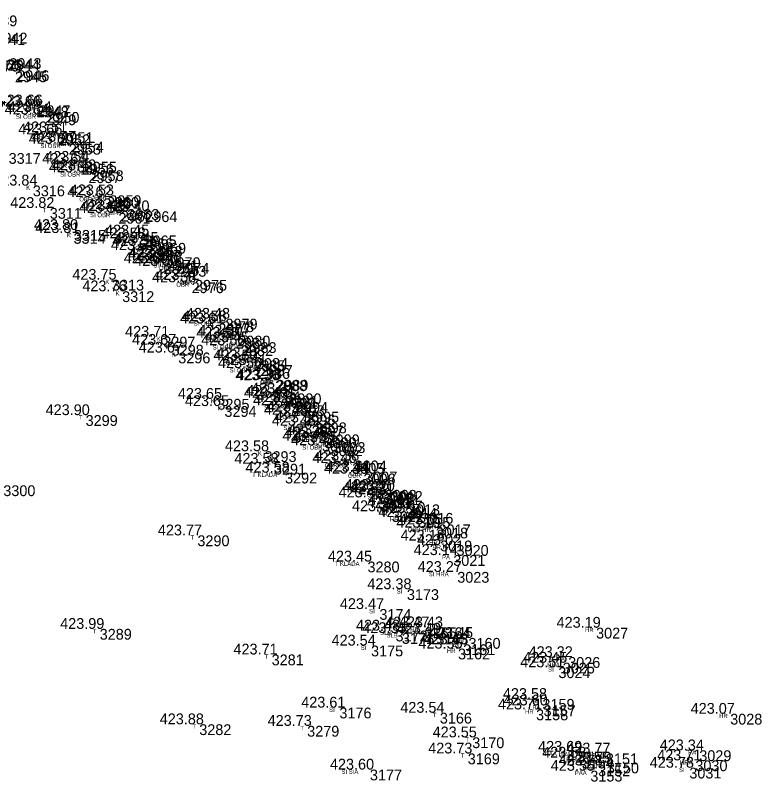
# Model space of a CAD drawing. Extents: x -639390 to -639075, y -1138747 to -1138358.
# Drawn here: x -639236.5 to -639184.6, y -1138516.9 to -1138463.7 of the extents above; entities that cross this region are included whole.
import ezdxf

# ---------------------------------------------------------------- set-up
doc = ezdxf.new("R2010")
doc.units = 0
for name, color, linetype in [('Vrstva 11', 7, 'Continuous'), ('Vrstva 12', 7, 'Continuous'), ('Vrstva 13', 7, 'Continuous'), ('Vrstva 57', 7, 'Continuous')]:
    doc.layers.add(name, color=color, linetype=linetype)

msp = doc.modelspace()

# ---------------------------------------------------------------- linework, layer by layer
at = {"layer": 'Vrstva 11'}
for p, q in [((-639235.32, -1138470), (-639235.32, -1138470)), ((-639235.19, -1138469.92), (-639235.19, -1138469.92)), ((-639234.79, -1138470.55), (-639234.79, -1138470.55)), ((-639234.57, -1138470.38), (-639234.57, -1138470.38)), ((-639233.83, -1138471.94), (-639233.83, -1138471.94)), ((-639233.6, -1138471.79), (-639233.6, -1138471.79)), ((-639233.08, -1138472.59), (-639233.08, -1138472.59)), ((-639232.88, -1138472.45), (-639232.88, -1138472.45)), ((-639232.18, -1138473.98), (-639232.18, -1138473.98)), ((-639231.97, -1138473.84), (-639231.97, -1138473.84)), ((-639231.71, -1138474.57), (-639231.71, -1138474.57)), ((-639231.5, -1138474.43), (-639231.5, -1138474.43)), ((-639235.58, -1138475.49), (-639235.58, -1138475.49)), ((-639230.43, -1138476.29), (-639230.43, -1138476.29)), ((-639230.26, -1138476.17), (-639230.26, -1138476.17)), ((-639234.4, -1138477.05), (-639234.4, -1138477.05)), ((-639229.63, -1138477.39), (-639229.63, -1138477.39)), ((-639229.46, -1138477.25), (-639229.46, -1138477.25)), ((-639229.02, -1138477.13), (-639229.02, -1138477.13)), ((-639227.76, -1138477.28), (-639227.76, -1138477.28)), ((-639232.75, -1138478.79), (-639232.75, -1138478.79)), ((-639232.72, -1138478.58), (-639232.72, -1138478.58)), ((-639227.81, -1138478.96), (-639227.81, -1138478.96)), ((-639228.05, -1138479.16), (-639228.05, -1138479.16)), ((-639227.16, -1138479.48), (-639227.16, -1138479.48)), ((-639227.5, -1138479.98), (-639227.5, -1138479.98)), ((-639227.4, -1138479.69), (-639227.4, -1138479.69)), ((-639226.3, -1138480.66), (-639226.3, -1138480.66)), ((-639226.15, -1138480.48), (-639226.15, -1138480.48)), ((-639226.48, -1138480.89), (-639226.48, -1138480.89)), ((-639225.75, -1138481.08), (-639225.75, -1138481.08)), ((-639225.54, -1138480.87), (-639225.54, -1138480.87)), ((-639230.08, -1138482.04), (-639230.08, -1138482.04)), ((-639224.54, -1138482.22), (-639224.54, -1138482.22)), ((-639224.31, -1138482.05), (-639224.31, -1138482.05)), ((-639229.37, -1138482.84), (-639229.37, -1138482.84)), ((-639222.43, -1138484.93), (-639222.43, -1138484.93)), ((-639222.19, -1138484.75), (-639222.19, -1138484.75)), ((-639222.69, -1138485.08), (-639222.69, -1138485.08)), ((-639226.51, -1138486), (-639226.51, -1138486)), ((-639221.3, -1138485.93), (-639221.3, -1138485.93)), ((-639221.47, -1138486.07), (-639221.47, -1138486.07)), ((-639220.87, -1138486.38), (-639220.87, -1138486.38)), ((-639225.93, -1138486.56), (-639225.93, -1138486.56)), ((-639221.11, -1138486.59), (-639221.11, -1138486.59)), ((-639225.47, -1138487.1), (-639225.47, -1138487.1)), ((-639220.07, -1138487.49), (-639220.07, -1138487.49)), ((-639220.25, -1138487.64), (-639220.25, -1138487.64)), ((-639219.74, -1138487.97), (-639219.74, -1138487.97)), ((-639219.93, -1138488.18), (-639219.93, -1138488.18)), ((-639218.73, -1138489.03), (-639218.73, -1138489.03)), ((-639218.66, -1138489), (-639218.66, -1138489)), ((-639218.16, -1138490.24), (-639218.16, -1138490.24)), ((-639217.99, -1138490.11), (-639217.99, -1138490.11)), ((-639217.75, -1138489.94), (-639217.75, -1138489.94)), ((-639222.75, -1138490.32), (-639222.75, -1138490.32)), ((-639217.53, -1138490.77), (-639217.53, -1138490.77)), ((-639217.29, -1138490.54), (-639217.29, -1138490.54)), ((-639222.26, -1138490.82), (-639222.26, -1138490.82)), ((-639216.52, -1138491.21), (-639216.52, -1138491.21)), ((-639231.91, -1138491.45), (-639231.91, -1138491.45)), ((-639216.77, -1138491.42), (-639216.77, -1138491.42)), ((-639216.2, -1138492.19), (-639216.2, -1138492.19)), ((-639215.99, -1138491.96), (-639215.99, -1138491.96)), ((-639215.09, -1138492.79), (-639215.09, -1138492.79)), ((-639215.48, -1138493.23), (-639215.48, -1138493.23)), ((-639215.31, -1138493), (-639215.31, -1138493)), ((-639214.69, -1138493.33), (-639214.69, -1138493.33)), ((-639219.48, -1138493.96), (-639219.48, -1138493.96)), ((-639214.88, -1138493.55), (-639214.88, -1138493.55)), ((-639218.82, -1138494.83), (-639218.82, -1138494.83)), ((-639213.38, -1138494.78), (-639213.38, -1138494.78)), ((-639213.21, -1138494.61), (-639213.21, -1138494.61)), ((-639218.05, -1138495.45), (-639218.05, -1138495.45)), ((-639212.6, -1138495.51), (-639212.6, -1138495.51)), ((-639212.48, -1138495.38), (-639212.48, -1138495.38)), ((-639211.13, -1138496.65), (-639211.13, -1138496.65)), ((-639211.58, -1138497.17), (-639211.58, -1138497.17)), ((-639211.3, -1138496.82), (-639211.3, -1138496.82)), ((-639210.88, -1138496.95), (-639210.88, -1138496.95)), ((-639210.71, -1138496.73), (-639210.71, -1138496.73)), ((-639209.51, -1138497.66), (-639209.51, -1138497.66)), ((-639210.63, -1138498.13), (-639210.63, -1138498.13)), ((-639209.71, -1138497.9), (-639209.71, -1138497.9)), ((-639208.58, -1138498.25), (-639208.58, -1138498.25)), ((-639208.79, -1138498.54), (-639208.79, -1138498.54)), ((-639207.56, -1138499.27), (-639207.56, -1138499.27)), ((-639207.38, -1138499.05), (-639207.38, -1138499.05)), ((-639224.14, -1138499.81), (-639224.14, -1138499.81)), ((-639207.27, -1138500.17), (-639207.27, -1138500.17)), ((-639206.13, -1138500.48), (-639206.13, -1138500.48)), ((-639206.36, -1138501.18), (-639206.36, -1138501.18)), ((-639212.32, -1138501.63), (-639212.32, -1138501.63)), ((-639206.08, -1138502.35), (-639206.08, -1138502.35)), ((-639209.58, -1138503.55), (-639209.58, -1138503.55)), ((-639211.49, -1138504.93), (-639211.49, -1138504.93)), ((-639208.34, -1138506.21), (-639208.34, -1138506.21)), ((-639207.39, -1138506.2), (-639207.39, -1138506.2)), ((-639196.43, -1138506.23), (-639196.43, -1138506.23)), ((-639230.93, -1138506.31), (-639230.93, -1138506.31)), ((-639210.37, -1138506.43), (-639210.37, -1138506.43)), ((-639209.93, -1138506.6), (-639209.93, -1138506.6)), ((-639207.53, -1138506.64), (-639207.53, -1138506.64)), ((-639205.3, -1138506.94), (-639205.3, -1138506.94)), ((-639212.07, -1138507.47), (-639212.07, -1138507.47)), ((-639206.03, -1138507.68), (-639206.03, -1138507.68)), ((-639205.67, -1138507.38), (-639205.67, -1138507.38)), ((-639218.98, -1138508.09), (-639218.98, -1138508.09)), ((-639198.37, -1138508.27), (-639198.37, -1138508.27)), ((-639198.75, -1138508.66), (-639198.75, -1138508.66)), ((-639199.05, -1138508.98), (-639199.05, -1138508.98)), ((-639200.16, -1138511.18), (-639200.16, -1138511.18)), ((-639214.27, -1138511.78), (-639214.27, -1138511.78)), ((-639200.6, -1138511.91), (-639200.6, -1138511.91)), ((-639200.08, -1138511.63), (-639200.08, -1138511.63)), ((-639207.29, -1138512.14), (-639207.29, -1138512.14)), ((-639187.11, -1138512.21), (-639187.11, -1138512.21)), ((-639224.01, -1138512.94), (-639224.01, -1138512.94)), ((-639216.51, -1138513.05), (-639216.51, -1138513.05)), ((-639205.04, -1138513.85), (-639205.04, -1138513.85)), ((-639189.26, -1138514.75), (-639189.26, -1138514.75)), ((-639205.35, -1138514.97), (-639205.35, -1138514.97)), ((-639197.71, -1138514.85), (-639197.71, -1138514.85)), ((-639197.43, -1138515.26), (-639197.43, -1138515.26)), ((-639195.75, -1138514.97), (-639195.75, -1138514.97)), ((-639196.29, -1138515.8), (-639196.29, -1138515.8)), ((-639195.68, -1138515.6), (-639195.68, -1138515.6)), ((-639189.53, -1138515.45), (-639189.53, -1138515.45)), ((-639212.15, -1138516.09), (-639212.15, -1138516.09)), ((-639196.83, -1138516.17), (-639196.83, -1138516.17)), ((-639189.95, -1138515.96), (-639189.95, -1138515.96))]:
    msp.add_line(p, q, dxfattribs=at)

# ---------------------------------------------------------------- texts
at = {"layer": 'Vrstva 12'}
for s, p in [('423.70 ', (-639239.319, -1138467.56)), ('423.66 ', (-639239.146, -1138467.48)), ('423.66 ', (-639237.806, -1138470)), ('423.66 ', (-639237.676, -1138469.92)), ('423.64 ', (-639237.259, -1138470.55)), ('423.54 ', (-639237.039, -1138470.38)), ('423.51 ', (-639235.975, -1138471.79)), ('423.66 ', (-639236.316, -1138471.94)), ('423.60 ', (-639235.579, -1138472.59)), ('423.47 ', (-639235.349, -1138472.45)), ('423.54 ', (-639234.439, -1138473.84)), ('423.64 ', (-639234.649, -1138473.98)), ('423.48 ', (-639233.969, -1138474.43)), ('423.63 ', (-639234.179, -1138474.57)), ('423.84 ', (-639238.049, -1138475.49)), ('423.62 ', (-639232.899, -1138476.29)), ('423.53 ', (-639232.729, -1138476.17)), ('423.82 ', (-639236.869, -1138477.05)), ('423.40 ', (-639231.519, -1138477.13)), ('423.58 ', (-639232.099, -1138477.39)), ('423.45 ', (-639231.93, -1138477.25)), ('423.40 ', (-639230.259, -1138477.28)), ('423.80 ', (-639235.219, -1138478.58)), ('423.81 ', (-639235.125, -1138478.79)), ('423.58 ', (-639230.519, -1138479.16)), ('423.45 ', (-639230.28, -1138478.96)), ('423.51 ', (-639229.775, -1138479.69)), ('423.45 ', (-639229.63, -1138479.48)), ('423.61 ', (-639229.875, -1138479.98)), ('423.60 ', (-639228.979, -1138480.89)), ('423.51 ', (-639228.675, -1138480.66)), ('423.45 ', (-639228.62, -1138480.48)), ('423.40 ', (-639228.039, -1138480.87)), ('423.50 ', (-639228.249, -1138481.08)), ('423.75 ', (-639232.55, -1138482.04)), ('423.58 ', (-639227.009, -1138482.22)), ('423.42 ', (-639226.779, -1138482.05)), ('423.76 ', (-639231.856, -1138482.84)), ('423.61 ', (-639225.065, -1138485.08)), ('423.58 ', (-639224.899, -1138484.93)), ('423.48 ', (-639224.659, -1138484.75)), ('423.71 ', (-639228.885, -1138486)), ('423.57 ', (-639223.939, -1138486.07)), ('423.50 ', (-639223.799, -1138485.93)), ('423.67 ', (-639228.399, -1138486.56)), ('423.56 ', (-639223.596, -1138486.59)), ('423.45 ', (-639223.34, -1138486.38)), ('423.67 ', (-639227.939, -1138487.1)), ('423.50 ', (-639222.749, -1138487.64)), ('423.42 ', (-639222.539, -1138487.49)), ('423.50 ', (-639222.429, -1138488.18)), ('423.41 ', (-639222.115, -1138487.97)), ('423.36 ', (-639221.216, -1138489.03)), ('423.33 ', (-639221.129, -1138489)), ('423.31 ', (-639220.125, -1138489.94)), ('423.65 ', (-639225.22, -1138490.32)), ('423.49 ', (-639220.629, -1138490.24)), ('423.45 ', (-639220.46, -1138490.11)), ('423.65 ', (-639224.73, -1138490.82)), ('423.48 ', (-639219.999, -1138490.77)), ('423.34 ', (-639219.759, -1138490.54)), ('423.90 ', (-639234.409, -1138491.45)), ('423.43 ', (-639219.239, -1138491.42)), ('423.30 ', (-639219.019, -1138491.21)), ('423.36 ', (-639218.476, -1138491.96)), ('423.46 ', (-639218.686, -1138492.19)), ('423.46 ', (-639217.796, -1138493)), ('423.35 ', (-639217.56, -1138492.79)), ('423.48 ', (-639217.949, -1138493.23)), ('423.47 ', (-639217.349, -1138493.55)), ('423.35 ', (-639217.16, -1138493.33)), ('423.58 ', (-639221.949, -1138493.96)), ('423.38 ', (-639215.679, -1138494.61)), ('423.58 ', (-639221.289, -1138494.83)), ('423.46 ', (-639215.866, -1138494.78)), ('423.58 ', (-639220.519, -1138495.45)), ('423.44 ', (-639215.069, -1138495.51)), ('423.44 ', (-639214.949, -1138495.38)), ('423.32 ', (-639213.769, -1138496.82)), ('423.26 ', (-639213.616, -1138496.65)), ('423.20 ', (-639213.209, -1138496.73)), ('423.43 ', (-639214.049, -1138497.17)), ('423.31 ', (-639213.255, -1138496.95)), ('423.31 ', (-639212.085, -1138497.9)), ('423.15 ', (-639211.98, -1138497.66)), ('423.36 ', (-639213.116, -1138498.13)), ('423.10 ', (-639211.079, -1138498.25)), ('423.26 ', (-639211.276, -1138498.54)), ('423.19 ', (-639210.029, -1138499.27)), ('423.05 ', (-639209.85, -1138499.05)), ('423.77 ', (-639226.609, -1138499.81)), ('423.18 ', (-639209.739, -1138500.17)), ('423.02 ', (-639208.599, -1138500.48)), ('423.45 ', (-639214.79, -1138501.63)), ('423.14 ', (-639208.829, -1138501.18)), ('423.27 ', (-639208.549, -1138502.35)), ('423.38 ', (-639212.049, -1138503.55)), ('423.47 ', (-639213.959, -1138504.93)), ('423.99 ', (-639233.399, -1138506.31)), ('423.48 ', (-639212.839, -1138506.43)), ('423.47 ', (-639210.809, -1138506.21)), ('423.43 ', (-639209.859, -1138506.2)), ('423.19 ', (-639198.899, -1138506.23)), ('423.35 ', (-639212.4, -1138506.6)), ('423.49 ', (-639209.999, -1138506.64)), ('423.45 ', (-639207.77, -1138506.94)), ('423.54 ', (-639214.539, -1138507.47)), ('423.45 ', (-639208.14, -1138507.38)), ('423.55 ', (-639208.5, -1138507.68)), ('423.71 ', (-639221.355, -1138508.09)), ('423.32 ', (-639200.839, -1138508.27)), ('423.51 ', (-639201.425, -1138508.98)), ('423.45 ', (-639201.22, -1138508.66)), ('423.58 ', (-639202.629, -1138511.18)), ('423.61 ', (-639216.645, -1138511.78)), ('423.60 ', (-639202.579, -1138511.63)), ('423.54 ', (-639209.759, -1138512.14)), ('423.71 ', (-639202.975, -1138511.91)), ('423.07 ', (-639189.579, -1138512.21)), ('423.88 ', (-639226.479, -1138512.94)), ('423.73 ', (-639218.979, -1138513.05)), ('423.55 ', (-639207.51, -1138513.85)), ('423.73 ', (-639207.819, -1138514.97)), ('423.69 ', (-639200.179, -1138514.85)), ('423.77 ', (-639198.219, -1138514.97)), ('423.34 ', (-639191.729, -1138514.75)), ('423.58 ', (-639199.899, -1138515.26)), ('423.71 ', (-639191.905, -1138515.45)), ('423.78 ', (-639198.759, -1138515.8)), ('423.79 ', (-639198.149, -1138515.6)), ('423.78 ', (-639192.419, -1138515.96)), ('423.60 ', (-639214.649, -1138516.09)), ('423.55 ', (-639199.3, -1138516.17))]:
    msp.add_text(s, height=0.75, dxfattribs=at).set_placement(p)
at = {"layer": 'Vrstva 13'}
for s, p in [(' 2939', (-639238.89, -1138464.42)), (' 2941', (-639238.34, -1138465.73)), (' 2942', (-639238.18, -1138465.62)), (' 2944', (-639237.33, -1138467.51)), (' 2943', (-639237.21, -1138467.39)), (' 2945', (-639236.82, -1138468.31)), (' 2946', (-639236.66, -1138468.23)), (' 2948', (-639235.32, -1138470.75)), (' 2947', (-639235.19, -1138470.67)), (' 2949', (-639234.79, -1138471.3)), (' 2950', (-639234.57, -1138471.13)), (' 2952', (-639233.83, -1138472.69)), (' 2951', (-639233.6, -1138472.54)), (' 2953', (-639233.08, -1138473.34)), (' 2954', (-639232.88, -1138473.2)), (' 3317', (-639237.26, -1138473.98)), (' 2956', (-639232.18, -1138474.73)), (' 2955', (-639231.97, -1138474.59)), (' 2957', (-639231.71, -1138475.32)), (' 2958', (-639231.5, -1138475.18)), (' 3316', (-639235.58, -1138476.24)), (' 2960', (-639230.43, -1138477.04)), (' 2959', (-639230.26, -1138476.92)), (' 3311', (-639234.4, -1138477.8)), (' 2961', (-639229.63, -1138478.14)), (' 2962', (-639229.46, -1138478)), (' 2963', (-639229.02, -1138477.88)), (' 2964', (-639227.76, -1138478.03)), (' 3314', (-639232.75, -1138479.54)), (' 3315', (-639232.72, -1138479.33)), (' 2965', (-639227.81, -1138479.71)), (' 2966', (-639228.05, -1138479.91)), (' 2969', (-639227.16, -1138480.23)), (' 2967', (-639227.5, -1138480.73)), (' 2968', (-639227.4, -1138480.44)), (' 2971', (-639226.3, -1138481.41)), (' 2970', (-639226.15, -1138481.23)), (' 2972', (-639226.48, -1138481.64)), (' 2973', (-639225.75, -1138481.83)), (' 2974', (-639225.54, -1138481.62)), (' 3313', (-639230.08, -1138482.79)), (' 2976', (-639224.54, -1138482.97)), (' 2975', (-639224.31, -1138482.8)), (' 3312', (-639229.37, -1138483.59)), (' 2978', (-639222.43, -1138485.68)), (' 2979', (-639222.19, -1138485.5)), (' 2977', (-639222.69, -1138485.83)), (' 3297', (-639226.51, -1138486.75)), (' 2980', (-639221.3, -1138486.68)), (' 2981', (-639221.47, -1138486.82)), (' 2983', (-639220.87, -1138487.13)), (' 3298', (-639225.93, -1138487.31)), (' 2982', (-639221.11, -1138487.34)), (' 3296', (-639225.47, -1138487.85)), (' 2984', (-639220.07, -1138488.24)), (' 2985', (-639220.25, -1138488.39)), (' 2987', (-639219.74, -1138488.72)), (' 2986', (-639219.93, -1138488.93)), (' 2988', (-639218.73, -1138489.78)), (' 2989', (-639218.66, -1138489.75)), (' 2992', (-639218.16, -1138490.99)), (' 2991', (-639217.99, -1138490.86)), (' 2990', (-639217.75, -1138490.69)), (' 3295', (-639222.75, -1138491.07)), (' 2993', (-639217.53, -1138491.52)), (' 2994', (-639217.29, -1138491.29)), (' 3294', (-639222.26, -1138491.57)), (' 2995', (-639216.52, -1138491.96)), (' 3299', (-639231.91, -1138492.2)), (' 2996', (-639216.77, -1138492.17)), (' 2997', (-639216.2, -1138492.94)), (' 2998', (-639215.99, -1138492.71)), (' 2999', (-639215.09, -1138493.54)), (' 3001', (-639215.48, -1138493.98)), (' 3000', (-639215.31, -1138493.75)), (' 3003', (-639214.69, -1138494.08)), (' 3293', (-639219.48, -1138494.71)), (' 3002', (-639214.88, -1138494.3)), (' 3291', (-639218.82, -1138495.58)), (' 3005', (-639213.38, -1138495.53)), (' 3004', (-639213.21, -1138495.36)), (' 3292', (-639218.05, -1138496.2)), (' 3006', (-639212.6, -1138496.26)), (' 3007', (-639212.48, -1138496.13)), (' 3300', (-639237.63, -1138497.08)), (' 3008', (-639211.13, -1138497.4)), (' 3010', (-639211.58, -1138497.92)), (' 3009', (-639211.3, -1138497.57)), (' 3011', (-639210.88, -1138497.7)), (' 3012', (-639210.71, -1138497.48)), (' 3013', (-639209.51, -1138498.41)), (' 3022', (-639210.63, -1138498.88)), (' 3014', (-639209.71, -1138498.65)), (' 3016', (-639208.58, -1138499)), (' 3015', (-639208.79, -1138499.29)), (' 3018', (-639207.56, -1138500.02)), (' 3017', (-639207.38, -1138499.8)), (' 3290', (-639224.14, -1138500.56)), (' 3019', (-639207.27, -1138500.92)), (' 3020', (-639206.13, -1138501.23)), (' 3021', (-639206.36, -1138501.93)), (' 3280', (-639212.32, -1138502.38)), (' 3023', (-639206.08, -1138503.1)), (' 3173', (-639209.58, -1138504.3)), (' 3174', (-639211.49, -1138505.68)), (' 3165', (-639208.34, -1138506.96)), (' 3164', (-639207.39, -1138506.95)), (' 3027', (-639196.43, -1138506.98)), (' 3289', (-639230.93, -1138507.06)), (' 3172', (-639210.37, -1138507.18)), (' 3171', (-639209.93, -1138507.35)), (' 3163', (-639207.53, -1138507.39)), (' 3160', (-639205.3, -1138507.69)), (' 3175', (-639212.07, -1138508.22)), (' 3162', (-639206.03, -1138508.43)), (' 3161', (-639205.67, -1138508.13)), (' 3281', (-639218.98, -1138508.84)), (' 3026', (-639198.37, -1138509.02)), (' 3025', (-639198.75, -1138509.41)), (' 3024', (-639199.05, -1138509.73)), (' 3159', (-639200.16, -1138511.93)), (' 3176', (-639214.27, -1138512.53)), (' 3158', (-639200.6, -1138512.66)), (' 3157', (-639200.08, -1138512.38)), (' 3166', (-639207.29, -1138512.89)), (' 3028', (-639187.11, -1138512.96)), (' 3282', (-639224.01, -1138513.69)), (' 3279', (-639216.51, -1138513.8)), (' 3170', (-639205.04, -1138514.6)), (' 3029', (-639189.26, -1138515.5)), (' 3169', (-639205.35, -1138515.72)), (' 3155', (-639197.71, -1138515.6)), (' 3154', (-639197.43, -1138516.01)), (' 3151', (-639195.75, -1138515.72)), (' 3152', (-639196.29, -1138516.55)), (' 3150', (-639195.68, -1138516.35)), (' 3030', (-639189.53, -1138516.2)), (' 3177', (-639212.15, -1138516.84)), (' 3153', (-639196.83, -1138516.92)), (' 3031', (-639189.95, -1138516.71))]:
    msp.add_text(s, height=0.75, dxfattribs=at).set_placement(p)
at = {"layer": 'Vrstva 57'}
for s, p in [('OBR', (-639235.979, -1138470.22)), ('SI', (-639235.758, -1138470.3)), ('SI OBR', (-639236.479, -1138470.85)), ('OBR', (-639235.359, -1138470.68)), ('OBR SI', (-639235.468, -1138472.24)), ('OBR', (-639234.389, -1138472.09)), ('SI OBR', (-639234.769, -1138472.89)), ('OBR', (-639233.669, -1138472.75)), ('OBR SI', (-639233.818, -1138474.28)), ('OBR', (-639232.759, -1138474.14)), ('SI OBR', (-639233.399, -1138474.87)), ('OBR', (-639232.289, -1138474.73)), ('K', (-639235.755, -1138475.79)), ('OBR SI', (-639232.068, -1138476.59)), ('OBR', (-639231.049, -1138476.47)), ('T', (-639234.6, -1138477.35)), ('SI OBR', (-639231.319, -1138477.69)), ('OBR', (-639230.249, -1138477.55)), ('SA', (-639229.52, -1138477.43)), ('SA', (-639228.26, -1138477.58)), ('K', (-639232.925, -1138479.09)), ('K', (-639232.895, -1138478.88)), ('OBR', (-639228.599, -1138479.26)), ('OBR SI', (-639229.688, -1138479.46)), ('OBR', (-639227.949, -1138479.78)), ('OBR', (-639228.189, -1138479.99)), ('SI', (-639227.938, -1138480.28)), ('OBR', (-639227.089, -1138480.96)), ('OBR', (-639226.939, -1138480.78)), ('SI', (-639226.918, -1138481.19)), ('OBR', (-639226.539, -1138481.38)), ('OBR', (-639226.329, -1138481.17)), ('K', (-639230.255, -1138482.34)), ('OBR', (-639225.329, -1138482.52)), ('OBR', (-639225.099, -1138482.35)), ('K', (-639229.545, -1138483.14)), ('SI OBR', (-639224.119, -1138485.23)), ('OBR', (-639222.979, -1138485.05)), ('SI', (-639223.128, -1138485.38)), ('K', (-639226.685, -1138486.3)), ('OBR', (-639222.089, -1138486.23)), ('OBR SI', (-639223.108, -1138486.37)), ('OBR', (-639221.659, -1138486.68)), ('T', (-639226.13, -1138486.86)), ('SI OBR', (-639222.799, -1138486.89)), ('K', (-639225.645, -1138487.4)), ('OBR', (-639220.859, -1138487.79)), ('OBR SI', (-639221.888, -1138487.94)), ('OBR', (-639220.529, -1138488.27)), ('SI OBR', (-639221.619, -1138488.48)), ('OBR', (-639219.519, -1138489.33)), ('OBR', (-639219.449, -1138489.3)), ('OBR', (-639218.779, -1138490.41)), ('SI', (-639218.598, -1138490.54)), ('OBR', (-639218.539, -1138490.24)), ('K', (-639222.925, -1138490.62)), ('SI OBR', (-639219.219, -1138491.07)), ('OBR', (-639218.079, -1138490.84)), ('K', (-639222.435, -1138491.12)), ('OBR', (-639217.309, -1138491.51)), ('T', (-639232.11, -1138491.75)), ('SI OBR', (-639218.459, -1138491.72)), ('SI OBR', (-639217.889, -1138492.49)), ('OBR', (-639216.779, -1138492.26)), ('OBR', (-639215.879, -1138493.09)), ('OBR SI', (-639216.948, -1138493.3)), ('SI', (-639215.918, -1138493.53)), ('OBR', (-639215.479, -1138493.63)), ('K', (-639219.655, -1138494.26)), ('SI OBR', (-639216.569, -1138493.85)), ('T', (-639219.02, -1138495.13)), ('OBR SI', (-639215.018, -1138495.08)), ('OBR', (-639213.999, -1138494.91)), ('T KLADA', (-639220.05, -1138495.75)), ('OBR', (-639213.389, -1138495.81)), ('OBR', (-639213.269, -1138495.68)), ('OBR', (-639211.919, -1138496.95)), ('OBR', (-639212.089, -1138497.12)), ('SI', (-639212.018, -1138497.47)), ('OBR', (-639211.669, -1138497.25)), ('OBR', (-639211.499, -1138497.03)), ('OBR', (-639210.299, -1138497.96)), ('OBR HR', (-639211.399, -1138498.2)), ('SI', (-639211.068, -1138498.43)), ('OBR', (-639209.369, -1138498.55)), ('HR OBR', (-639210.479, -1138498.84)), ('OBR HR', (-639209.249, -1138499.57)), ('OBR', (-639208.169, -1138499.35)), ('T', (-639224.34, -1138500.11)), ('HR', (-639207.759, -1138500.47)), ('HR PA', (-639207.53, -1138500.78)), ('PA', (-639206.86, -1138501.48)), ('T KLADA', (-639214.32, -1138501.93)), ('SI HRA', (-639207.78, -1138502.65)), ('SI', (-639210.018, -1138503.85)), ('SI', (-639211.928, -1138505.23)), ('PA HR', (-639209.729, -1138506.51)), ('PA', (-639207.89, -1138506.5)), ('HR', (-639196.919, -1138506.53)), ('T', (-639231.13, -1138506.61)), ('SLB', (-639211.159, -1138506.73)), ('SLB', (-639210.719, -1138506.9)), ('HR', (-639208.019, -1138506.94)), ('SI', (-639205.738, -1138507.24)), ('SI', (-639212.508, -1138507.77)), ('HR', (-639206.519, -1138507.98)), ('PA', (-639206.17, -1138507.68)), ('T', (-639219.18, -1138508.39)), ('PA', (-639198.87, -1138508.57)), ('HRA', (-639199.55, -1138508.96)), ('SI', (-639199.488, -1138509.28)), ('SI', (-639200.598, -1138511.48)), ('SI', (-639214.708, -1138512.08)), ('HR', (-639201.089, -1138512.21)), ('PA', (-639200.58, -1138511.93)), ('T', (-639207.49, -1138512.44)), ('HR', (-639187.599, -1138512.51)), ('T', (-639224.21, -1138513.24)), ('T', (-639216.71, -1138513.35)), ('T', (-639205.24, -1138514.15)), ('PA', (-639189.76, -1138515.05)), ('T', (-639205.55, -1138515.27)), ('PAA HRA', (-639199.71, -1138515.15)), ('PAA', (-639198.23, -1138515.56)), ('HR PA', (-639197.15, -1138515.27)), ('HRA', (-639197.09, -1138516.1)), ('HR', (-639196.169, -1138515.9)), ('HRA', (-639190.33, -1138515.75)), ('SI SIA', (-639213.85, -1138516.39)), ('PAA', (-639197.63, -1138516.47)), ('SI', (-639190.388, -1138516.26))]:
    msp.add_text(s, height=0.3, dxfattribs=at).set_placement(p)

doc.saveas('drawing.dxf')
